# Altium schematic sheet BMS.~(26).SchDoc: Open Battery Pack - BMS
size A3; Date: 26/03/2019; Author: Morgane Vallée - Samuel Lesueur; Revision: 1.0; SheetNumber: 1; SheetTotal: 3
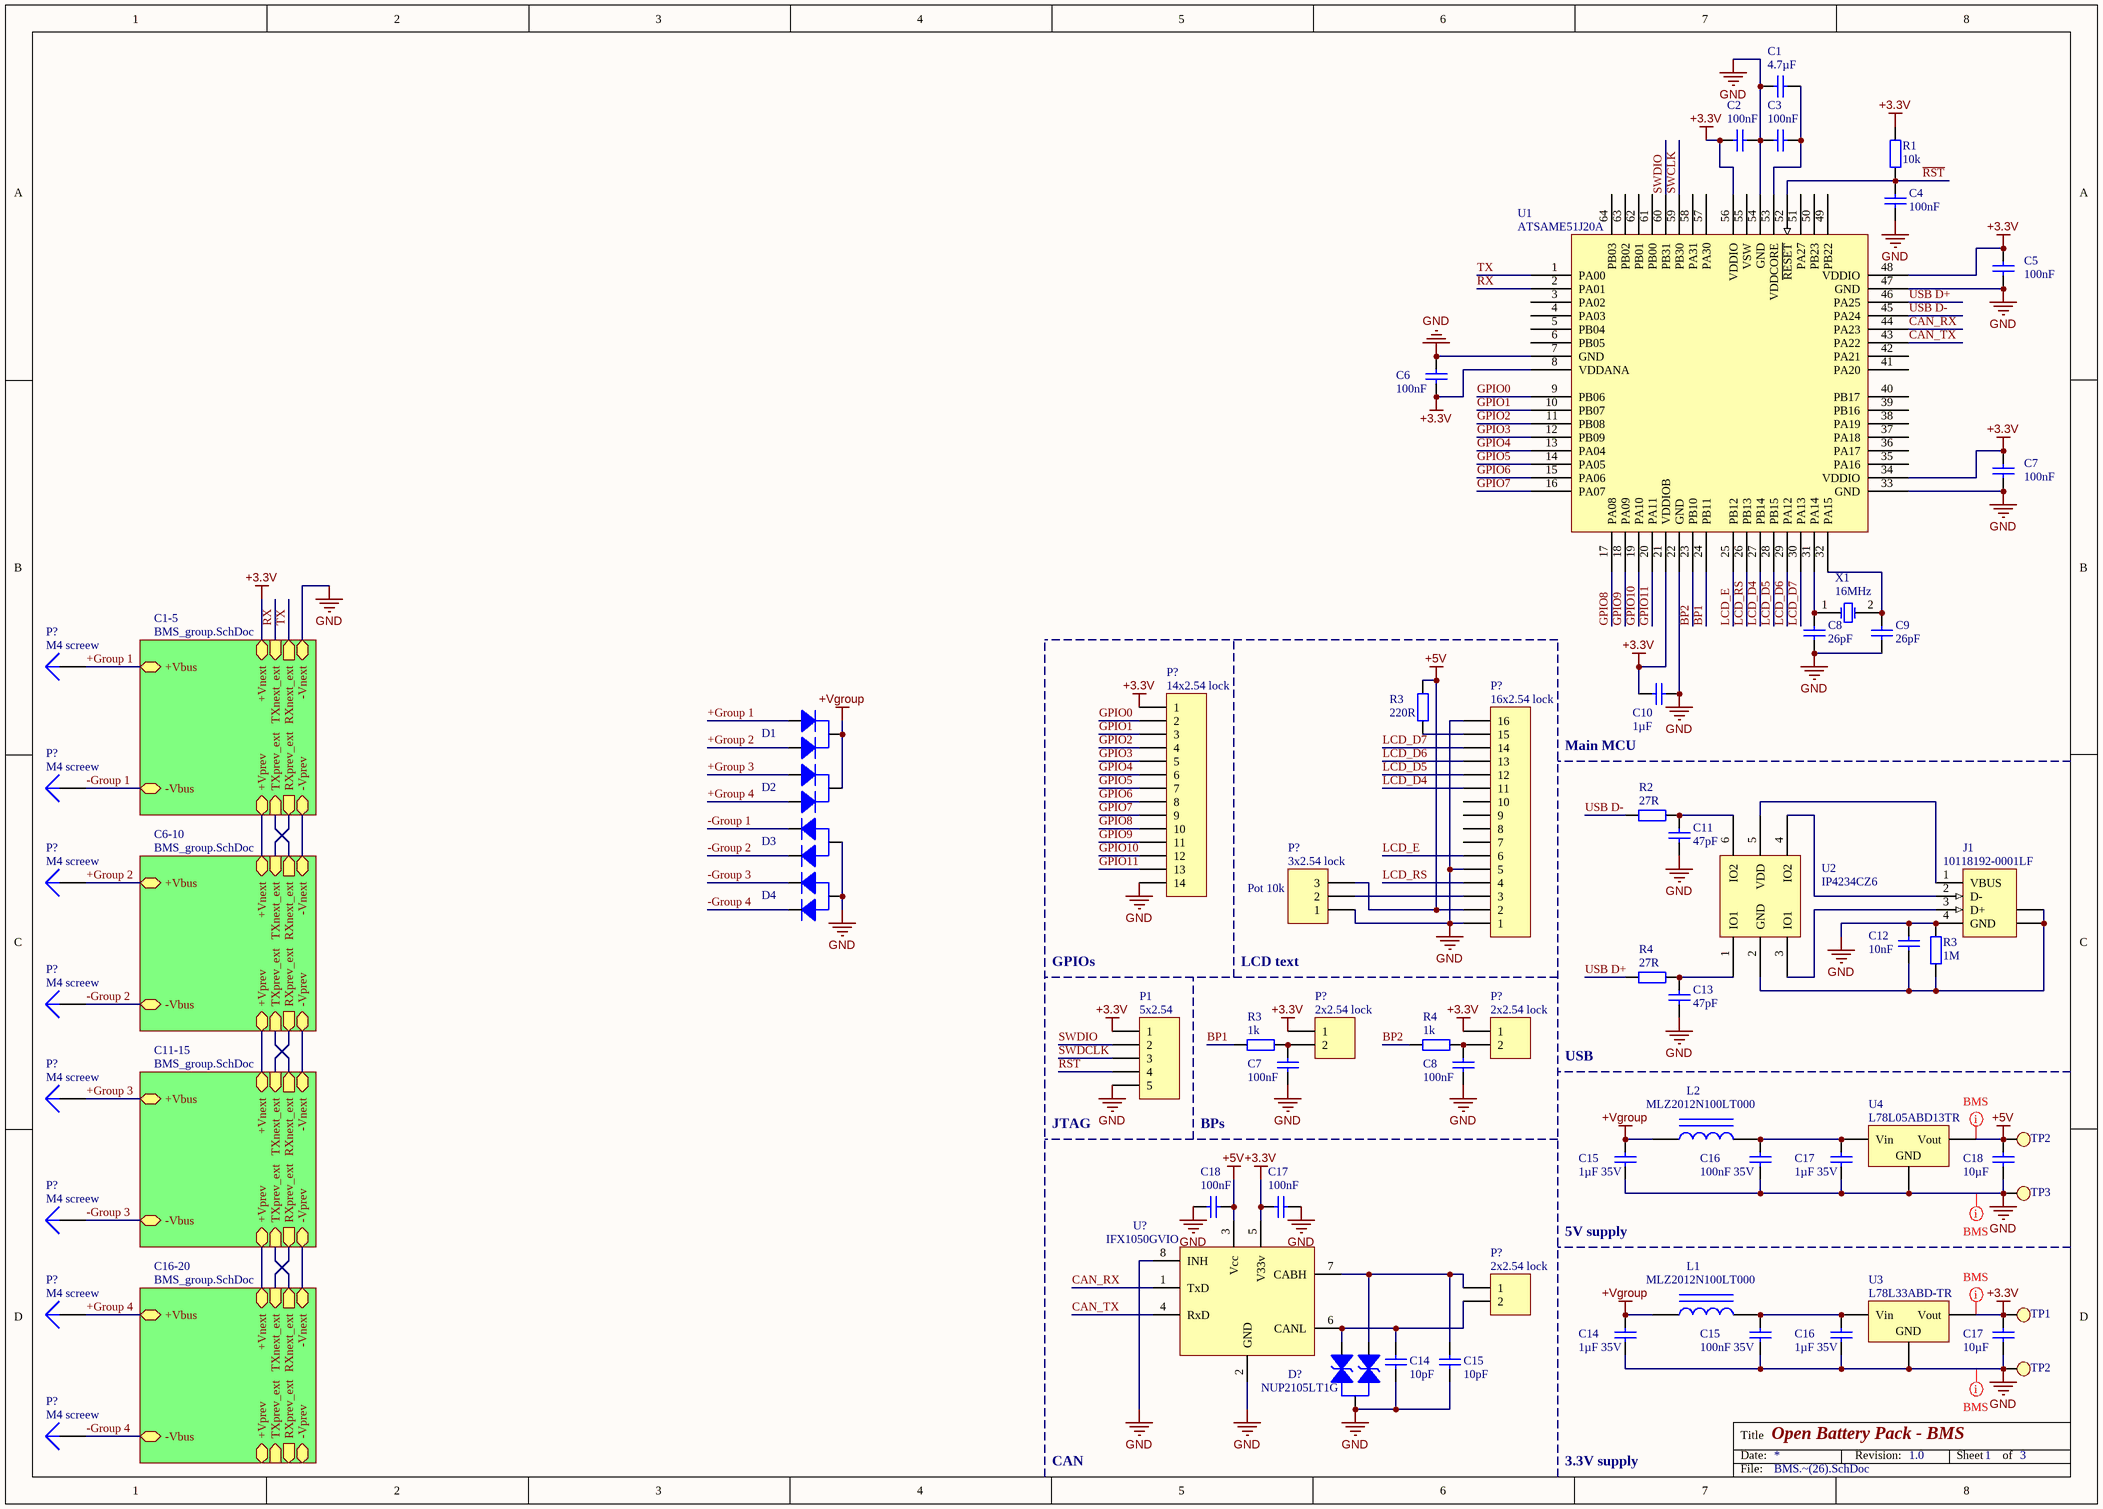
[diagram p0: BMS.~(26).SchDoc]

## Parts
(Parts that share a designator on the sheet are numbered #1, #2 ... from top to bottom, then left to right.)
C1  4.7µF  [C0603]
C2  100nF  [C0603]
C3  100nF  [C0603]
C4  100nF  [C0603]
C5  100nF  [C0603]
C6  100nF  [C0603]
C7#1  100nF  [C0603]
C7#2  100nF  [C0603]
C8#1  26pF  [C0603]
C8#2  100nF  [C0603]
C9  26pF  [C0603]
C10  1µF  [C0603]
C11  47pF  [C0603]
C12  10nF  [C0603]
C13  47pF  [C0603]
C14#1  1µF 35V  [C0603]
C14#2  10pF  [C0603]
C15#1  1µF 35V  [C0603]
C15#2  100nF 35V  [C0603]
C15#3  10pF  [C0603]
C16#1  100nF 35V  [C0603]
C16#2  1µF 35V  [C0603]
C17#1  1µF 35V  [C0603]
C17#2  100nF  [C0603]
C17#3  10µF  [C0603]
C18#1  10µF  [C0603]
C18#2  100nF  [C0603]
D1  (no value)  [DIODES SOT-23-3]
D2  (no value)  [DIODES SOT-23-3]
D3  (no value)  [DIODES SOT-23-3]
D4  (no value)  [DIODES SOT-23-3]
D?  NUP2105LT1G  [DIODES SOT-23-3]
J1  10118192-0001LF  [353576]
L1  MLZ2012N100LT000  [AXIAL-0.9]
L2  MLZ2012N100LT000  [AXIAL-0.9]
P1  5x2.54  [HDR1X5]
P?#1  M4 screew  [HOLE_4]
P?#2  14x2.54 lock  [HDR1X14]
P?#3  M4 screew  [HOLE_4]
P?#4  M4 screew  [HOLE_4]
P?#5  3x2.54 lock  [MOLEX KK 0022272031]
P?#6  16x2.54 lock  [HDR1X16]
P?#7  M4 screew  [HOLE_4]
P?#8  2x2.54 lock  [MOLEX KK 0022272021]
P?#9  2x2.54 lock  [MOLEX KK 0022272021]
P?#10  M4 screew  [HOLE_4]
P?#11  M4 screew  [HOLE_4]
P?#12  2x2.54 lock  [FCI 06-381-2PIN]
P?#13  M4 screew  [HOLE_4]
P?#14  M4 screew  [HOLE_4]
R1  10k  [R0603]
R2  27R  [R0603]
R3#1  220R  [R0603]
R3#2  1M  [R0603]
R3#3  1k  [R0603]
R4#1  27R  [R0603]
R4#2  1k  [R0603]
TP1  Test Point  [Test Point]  (value not drawn)
TP2#1  Test Point  [Test Point]  (value not drawn)
TP2#2  Test Point  [Test Point]  (value not drawn)
TP3  Test Point  [Test Point]  (value not drawn)
U1  ATSAME51J20A  [TQFP-64N]
U2  IP4234CZ6  [VISHAY TSOP-6 MO-193C]
U3  L78L33ABD-TR  [ST SOIC-8N]
U4  L78L05ABD13TR  [ST SOIC-8N]
U?  IFX1050GVIO  [INFINEON SO-8]
X1  16MHz  [ABRACON ABLS]

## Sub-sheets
C1-5 = BMS_group.SchDoc: -Vprev, RXnext_ext (out), +Vnext, -Vnext, TXnext_ext (in), RXprev_ext (out), +Vprev, TXprev_ext (in), -Vbus, +Vbus
C6-10 = BMS_group.SchDoc: -Vprev, RXnext_ext (out), +Vnext, -Vnext, TXnext_ext (in), RXprev_ext (out), +Vprev, TXprev_ext (in), -Vbus, +Vbus
C11-15 = BMS_group.SchDoc: -Vprev, RXnext_ext (out), +Vnext, -Vnext, TXnext_ext (in), RXprev_ext (out), +Vprev, TXprev_ext (in), -Vbus, +Vbus
C16-20 = BMS_group.SchDoc: -Vprev, RXnext_ext (out), +Vnext, -Vnext, TXnext_ext (in), RXprev_ext (out), +Vprev, TXprev_ext (in), -Vbus, +Vbus

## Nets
+3.3V: C2.2 C5.2 C6.1 C7#1.2 C10.2 C17#2.1 C17#3.1 P1.1 P?#2.1 P?#8.1 P?#9.1 R1.2 TP1.1 U1.8(VDDANA) U1.21(VDDIOB) U1.34(VDDIO) U1.48(VDDIO) U1.56(VDDIO) U3.3(Vout) U?.5(V33v) ; sheet C1-5/+Vnext
+5V: C18#1.1 C18#2.2 P?#5.3 P?#6.2 R3#1.2 TP2#1.1 U4.3(Vout) U?.3(Vcc)
+Vgroup: C14#1.1 C15#1.1 D1.3(K) D2.3(K) L1.1 L2.1
GND: C1.2 C2.1 C3.2 C4.1 C5.1 C6.2 C7#1.1 C7#2.1 C8#1.1 C8#2.1 C9.1 C10.1 C11.1 C12.2 C13.1 C14#1.2 C14#2.1 C15#1.2 C15#2.2 C15#3.1 C16#1.2 C16#2.2 C17#1.2 C17#2.2 C17#3.2 C18#1.2 C18#2.1 D3.3(A) D4.3(A) D?.3 J1.4(GND) P1.5 P?#2.14 P?#5.1 P?#6.1 P?#6.5 P?#6.16 R3#2.1 TP2#2.1 TP3.1 U1.7(GND) U1.22(GND) U1.33(GND) U1.47(GND) U1.54(GND) U3.2(GND) U4.2(GND) U?.2(GND) U?.8(INH) ; sheet C1-5/-Vnext
+Group 1: D1.1(A1) P?#1.1 ; sheet C1-5/+Vbus
+Group 2: D1.2(A2) P?#4.1 ; sheet C6-10/+Vbus
+Group 3: D2.1(A1) P?#10.1 ; sheet C11-15/+Vbus
+Group 4: D2.2(A2) P?#13.1 ; sheet C16-20/+Vbus
-Group 1: D3.2(K2) P?#3.1 ; sheet C1-5/-Vbus
-Group 2: D3.1(K1) P?#7.1 ; sheet C6-10/-Vbus
-Group 3: D4.2(K2) P?#11.1 ; sheet C11-15/-Vbus
-Group 4: D4.1(K1) P?#14.1 ; sheet C16-20/-Vbus
BP1: R3#3.1 U1.24(PB11)
BP2: R4#2.1 U1.23(PB10)
CAN_RX: U1.44(PA23) U?.1(TxD)
CAN_TX: U1.43(PA22) U?.4(RxD)
GPIO0: P?#2.2 U1.9(PB06)
GPIO1: P?#2.3 U1.10(PB07)
GPIO2: P?#2.4 U1.11(PB08)
GPIO3: P?#2.5 U1.12(PB09)
GPIO4: P?#2.6 U1.13(PA04)
GPIO5: P?#2.7 U1.14(PA05)
GPIO6: P?#2.8 U1.15(PA06)
GPIO7: P?#2.9 U1.16(PA07)
GPIO8: P?#2.10 U1.17(PA08)
GPIO9: P?#2.11 U1.18(PA09)
GPIO10: P?#2.12 U1.19(PA10)
GPIO11: P?#2.13 U1.20(PA11)
LCD_D4: P?#6.11 U1.27(PB14)
LCD_D5: P?#6.12 U1.28(PB15)
LCD_D6: P?#6.13 U1.29(PA12)
LCD_D7: P?#6.14 U1.30(PA13)
LCD_E: P?#6.6 U1.25(PB12)
LCD_RS: P?#6.4 U1.26(PB13)
~{RST}: C4.2 P1.4 R1.1 U1.52(~{RESET})
RX: U1.2(PA01) ; sheet C1-5/TXnext_ext
SWCLK: U1.59(PB30)
SWDCLK: P1.3
SWDIO: P1.2 U1.60(PB31)
TX: U1.1(PA00) ; sheet C1-5/RXnext_ext
USB D+: R4#1.1 U1.46(PA25)
USB D-: R2.1 U1.45(PA24)
NetC1_1: C1.1 C3.1 U1.53(VDDCORE)
NetC7#2_2: C7#2.2 P?#8.2 R3#3.2
NetC8#1_2: C8#1.2 U1.31(PA14) X1.1(OSC1)
NetC8#2_2: C8#2.2 P?#9.2 R4#2.2
NetC9_2: C9.2 U1.32(PA15) X1.2(OSC2)
NetC11_2: C11.2 R2.2 U2.6(IO2)
NetC12_1: C12.1 J1.5(SHLD) J1.6(SHLD) R3#2.2 U2.2(GND)
NetC13_2: C13.2 R4#1.2 U2.1(IO1)
NetC14#2_2: C14#2.2 D?.2 P?#12.2 U?.6(CANL)
NetC15#2_1: C15#2.1 C16#2.1 L1.2 U3.1(Vin)
NetC15#3_2: C15#3.2 D?.1 P?#12.1 U?.7(CABH)
NetC16#1_1: C16#1.1 C17#1.1 L2.2 U4.1(Vin)
NetJ1_1: J1.1(VBUS) U2.5(VDD)
NetJ1_2: J1.2(D-) U2.4(IO2)
NetJ1_3: J1.3(D+) U2.3(IO1)
NetP?#5_2: P?#5.2 P?#6.3
NetP?#6_15: P?#6.15 R3#1.1
(unnamed): sheet C1-5/-Vprev, sheet C6-10/-Vnext
(unnamed): sheet C1-5/RXprev_ext, sheet C6-10/TXnext_ext  [a separate net that carries the same name]
(unnamed): sheet C1-5/+Vprev, sheet C6-10/+Vnext  [a separate net that carries the same name]
(unnamed): sheet C1-5/TXprev_ext, sheet C6-10/RXnext_ext  [a separate net that carries the same name]
(unnamed): sheet C6-10/-Vprev, sheet C11-15/-Vnext  [a separate net that carries the same name]
(unnamed): sheet C6-10/RXprev_ext, sheet C11-15/TXnext_ext  [a separate net that carries the same name]
(unnamed): sheet C6-10/+Vprev, sheet C11-15/+Vnext  [a separate net that carries the same name]
(unnamed): sheet C6-10/TXprev_ext, sheet C11-15/RXnext_ext  [a separate net that carries the same name]
(unnamed): sheet C11-15/-Vprev, sheet C16-20/-Vnext  [a separate net that carries the same name]
(unnamed): sheet C11-15/RXprev_ext, sheet C16-20/TXnext_ext  [a separate net that carries the same name]
(unnamed): sheet C11-15/+Vprev, sheet C16-20/+Vnext  [a separate net that carries the same name]
(unnamed): sheet C11-15/TXprev_ext, sheet C16-20/RXnext_ext  [a separate net that carries the same name]

Not connected (* = marked no-connect by the designer): P?#6 7 8 9 10; U1 3(PA02) 4(PA03) 5(PB04) 6(PB05) 35(PA16) 36(PA17) 37(PA18) 38(PA19) 39(PB16) 40(PB17) 41(PA20) 42(PA21) 49(PB22) 50(PB23) 51(PA27) 55(VSW) 57(PA30) 58(PA31) 61(PB00) 62(PB01) 63(PB02) 64(PB03)

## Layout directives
net class BMS: +3.3V, +5V, GND

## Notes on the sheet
- Main MCU
- (near P?#5) Pot 10k
- GPIOs
- (near P?#5) LCD text
- JTAG
- BPs
- USB
- 5V supply
- CAN
- 3.3V supply

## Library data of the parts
C1-C6 C7#1 C7#2 C8#1 C8#2 C9-C13 C14#1 C14#2 C15#1-C15#3 C16#1 C16#2 C17#1-C17#3 C18#1 C18#2 = Cap: Capacitor
D1 D2 = Diode dual C: Diode 2 common Cathode
D3 D4 = Diode dual A: Diode 2 common Anode
D? = Dual Line TVS
J1 = 1-353576-1: USB 1.1, Right Angle, SMT, A Type, Receptacle, 4 Position, White
L1 L2 = Inductor Iron: Magnetic-Core Inductor
P1 = Header 5: Header, 5-Pin
P?#1 P?#3 P?#4 P?#7 P?#10 P?#11 P?#13 P?#14 = Plug
P?#2 = Header 14: Header, 14-Pin
P?#5 = Header 3: Header, 3-Pin
P?#6 = Header 16: Header, 16-Pin
P?#8 P?#9 = Header 2: Header, 2-Pin
P?#12 = Header 2H: Header, 2-Pin, Right Angle
R1 R2 R3#1-R3#3 R4#1 R4#2 = Res2: Resistor
U2 = IP4234CZ6: Single USB 2.0 ESD protection to IEC 61000-4-2 level 4
U3 U4 = Volt Reg: Voltage Regulator; pin to pad: 1>8 2>2+3+6+7 3>1
U? = IFX1050GVIO: High Speed CAN-Transceiver
X1 = XTAL: Crystal Oscillator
